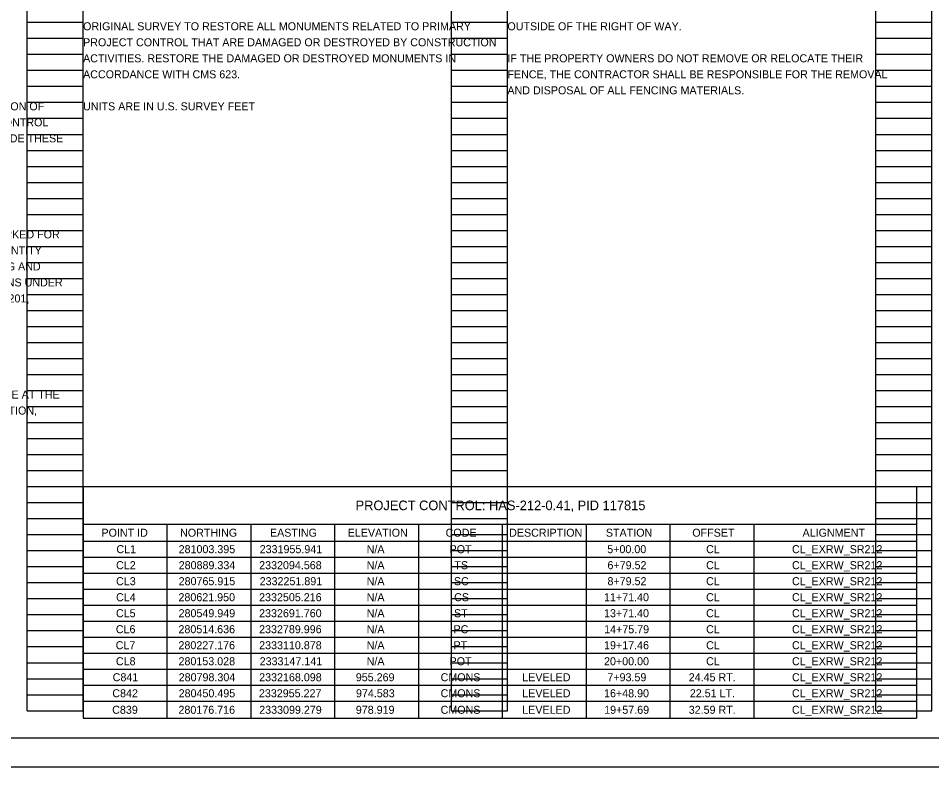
# Model space of a CAD drawing. Extents: x -3.4 to 43.7, y 0 to 26.
# Drawn here: x 8.69 to 24.66, y 0 to 13.09 of the extents above; entities that cross this region are included whole.
import ezdxf

# ---------------------------------------------------------------- set-up
doc = ezdxf.new("R2010")
doc.units = 0
for name, color, linetype in [('SH_Border', 7, 'Continuous'), ('SH_Cut_Line', 7, 'Continuous'), ('SH_Data', 7, 'Continuous'), ('SH_Text', 7, 'Continuous')]:
    doc.layers.add(name, color=color, linetype=linetype)

msp = doc.modelspace()

# ---------------------------------------------------------------- linework, layer by layer
at = {"layer": 'SH_Border'}
msp.add_lwpolyline([(1.5, 21.5), (33.5, 21.5), (33.5, 0.5), (1.5, 0.5)], close=True, dxfattribs=at)
at = {"layer": 'SH_Cut_Line'}
msp.add_lwpolyline([(0, 0), (34, 0), (34, 22), (0, 22)], close=True, dxfattribs=at)
at = {"layer": 'SH_Data'}
for p, q in [((8.84, 0.98), (8.84, 21.14)), ((9.82, 0.98), (9.82, 21.14)), ((16.26, 0.98), (16.26, 21.14)), ((17.24, 0.98), (17.24, 21.14)), ((23.68, 0.98), (23.68, 21.14)), ((24.66, 0.98), (24.66, 21.14)), ((8.84, 13.02), (9.82, 13.02)), ((16.26, 13.02), (17.24, 13.02)), ((23.68, 13.02), (24.66, 13.02)), ((8.84, 12.74), (9.82, 12.74)), ((16.26, 12.74), (17.24, 12.74)), ((23.68, 12.74), (24.66, 12.74)), ((8.84, 12.46), (9.82, 12.46)), ((16.26, 12.46), (17.24, 12.46)), ((23.68, 12.46), (24.66, 12.46)), ((8.84, 12.18), (9.82, 12.18)), ((16.26, 12.18), (17.24, 12.18)), ((23.68, 12.18), (24.66, 12.18)), ((8.84, 11.9), (9.82, 11.9)), ((16.26, 11.9), (17.24, 11.9)), ((23.68, 11.9), (24.66, 11.9)), ((8.84, 11.62), (9.82, 11.62)), ((16.26, 11.62), (17.24, 11.62)), ((23.68, 11.62), (24.66, 11.62)), ((8.84, 11.34), (9.82, 11.34)), ((16.26, 11.34), (17.24, 11.34)), ((23.68, 11.34), (24.66, 11.34)), ((8.84, 11.06), (9.82, 11.06)), ((16.26, 11.06), (17.24, 11.06)), ((23.68, 11.06), (24.66, 11.06)), ((8.84, 10.78), (9.82, 10.78)), ((16.26, 10.78), (17.24, 10.78)), ((23.68, 10.78), (24.66, 10.78)), ((8.84, 10.5), (9.82, 10.5)), ((16.26, 10.5), (17.24, 10.5)), ((23.68, 10.5), (24.66, 10.5)), ((8.84, 10.22), (9.82, 10.22)), ((16.26, 10.22), (17.24, 10.22)), ((23.68, 10.22), (24.66, 10.22)), ((8.84, 9.94), (9.82, 9.94)), ((16.26, 9.94), (17.24, 9.94)), ((23.68, 9.94), (24.66, 9.94)), ((8.84, 9.66), (9.82, 9.66)), ((16.26, 9.66), (17.24, 9.66)), ((23.68, 9.66), (24.66, 9.66)), ((8.84, 9.38), (9.82, 9.38)), ((16.26, 9.38), (17.24, 9.38)), ((23.68, 9.38), (24.66, 9.38)), ((8.84, 9.1), (9.82, 9.1)), ((16.26, 9.1), (17.24, 9.1)), ((23.68, 9.1), (24.66, 9.1)), ((8.84, 8.82), (9.82, 8.82)), ((16.26, 8.82), (17.24, 8.82)), ((23.68, 8.82), (24.66, 8.82)), ((8.84, 8.54), (9.82, 8.54)), ((16.26, 8.54), (17.24, 8.54)), ((23.68, 8.54), (24.66, 8.54)), ((8.84, 8.26), (9.82, 8.26)), ((16.26, 8.26), (17.24, 8.26)), ((23.68, 8.26), (24.66, 8.26)), ((8.84, 7.98), (9.82, 7.98)), ((16.26, 7.98), (17.24, 7.98)), ((23.68, 7.98), (24.66, 7.98)), ((8.84, 7.7), (9.82, 7.7)), ((16.26, 7.7), (17.24, 7.7)), ((23.68, 7.7), (24.66, 7.7)), ((8.84, 7.42), (9.82, 7.42)), ((16.26, 7.42), (17.24, 7.42)), ((23.68, 7.42), (24.66, 7.42)), ((8.84, 7.14), (9.82, 7.14)), ((16.26, 7.14), (17.24, 7.14)), ((23.68, 7.14), (24.66, 7.14)), ((8.84, 6.86), (9.82, 6.86)), ((16.26, 6.86), (17.24, 6.86)), ((23.68, 6.86), (24.66, 6.86)), ((8.84, 6.58), (9.82, 6.58)), ((16.26, 6.58), (17.24, 6.58)), ((23.68, 6.58), (24.66, 6.58)), ((8.84, 6.3), (9.82, 6.3)), ((16.26, 6.3), (17.24, 6.3)), ((23.68, 6.3), (24.66, 6.3)), ((8.84, 6.02), (9.82, 6.02)), ((16.26, 6.02), (17.24, 6.02)), ((23.68, 6.02), (24.66, 6.02)), ((8.84, 5.74), (9.82, 5.74)), ((16.26, 5.74), (17.24, 5.74)), ((23.68, 5.74), (24.66, 5.74)), ((8.84, 5.46), (9.82, 5.46)), ((16.26, 5.46), (17.24, 5.46)), ((23.68, 5.46), (24.66, 5.46)), ((8.84, 5.18), (9.82, 5.18)), ((16.26, 5.18), (17.24, 5.18)), ((23.68, 5.18), (24.66, 5.18)), ((8.84, 4.9), (9.82, 4.9)), ((16.26, 4.9), (17.24, 4.9)), ((23.68, 4.9), (24.66, 4.9)), ((8.84, 4.62), (9.82, 4.62)), ((16.26, 4.62), (17.24, 4.62)), ((23.68, 4.62), (24.66, 4.62)), ((8.84, 4.34), (9.82, 4.34)), ((16.26, 4.34), (17.24, 4.34)), ((23.68, 4.34), (24.66, 4.34)), ((8.84, 4.06), (9.82, 4.06)), ((16.26, 4.06), (17.24, 4.06)), ((23.68, 4.06), (24.66, 4.06)), ((8.84, 3.78), (9.82, 3.78)), ((16.26, 3.78), (17.24, 3.78)), ((23.68, 3.78), (24.66, 3.78)), ((8.84, 3.5), (9.82, 3.5)), ((16.26, 3.5), (17.24, 3.5)), ((23.68, 3.5), (24.66, 3.5)), ((8.84, 3.22), (9.82, 3.22)), ((16.26, 3.22), (17.24, 3.22)), ((23.68, 3.22), (24.66, 3.22)), ((8.84, 2.94), (9.82, 2.94)), ((16.26, 2.94), (17.24, 2.94)), ((23.68, 2.94), (24.66, 2.94)), ((8.84, 2.66), (9.82, 2.66)), ((16.26, 2.66), (17.24, 2.66)), ((23.68, 2.66), (24.66, 2.66)), ((8.84, 2.38), (9.82, 2.38)), ((16.26, 2.38), (17.24, 2.38)), ((23.68, 2.38), (24.66, 2.38)), ((8.84, 2.1), (9.82, 2.1)), ((16.26, 2.1), (17.24, 2.1)), ((23.68, 2.1), (24.66, 2.1)), ((8.84, 1.82), (9.82, 1.82)), ((16.26, 1.82), (17.24, 1.82)), ((23.68, 1.82), (24.66, 1.82)), ((8.84, 1.54), (9.82, 1.54)), ((16.26, 1.54), (17.24, 1.54)), ((23.68, 1.54), (24.66, 1.54)), ((8.84, 1.26), (9.82, 1.26)), ((16.26, 1.26), (17.24, 1.26)), ((23.68, 1.26), (24.66, 1.26)), ((8.84, 0.98), (9.82, 0.98)), ((16.26, 0.98), (17.24, 0.98)), ((23.68, 0.98), (24.66, 0.98))]:
    msp.add_line(p, q, dxfattribs=at)
at = {"layer": 'SH_Text'}
for p, q in [((9.82, 4.9), (24.396, 4.9)), ((9.82, 4.9), (9.82, 0.848)), ((24.396, 4.9), (24.396, 0.848)), ((9.82, 4.241), (24.396, 4.241)), ((11.286, 4.241), (11.286, 0.848)), ((12.752, 4.241), (12.752, 0.848)), ((14.218, 4.241), (14.218, 0.848)), ((15.684, 4.241), (15.684, 0.848)), ((17.149, 4.241), (17.149, 0.848)), ((18.615, 4.241), (18.615, 0.848)), ((20.081, 4.241), (20.081, 0.848)), ((21.547, 4.241), (21.547, 0.848)), ((9.82, 3.945), (24.396, 3.945)), ((9.82, 3.665), (24.396, 3.665)), ((9.82, 3.385), (24.396, 3.385)), ((9.82, 3.105), (24.396, 3.105)), ((9.82, 2.825), (24.396, 2.825)), ((9.82, 2.545), (24.396, 2.545)), ((9.82, 2.265), (24.396, 2.265)), ((9.82, 1.985), (24.396, 1.985)), ((9.82, 1.705), (24.396, 1.705)), ((9.82, 1.425), (24.396, 1.425)), ((9.82, 1.145), (24.396, 1.145)), ((9.82, 0.848), (24.396, 0.848))]:
    msp.add_line(p, q, dxfattribs=at)

# ---------------------------------------------------------------- texts
for s, height, p in [('ORIGINAL SURVEY TO RESTORE ALL MONUMENTS RELATED TO PRIMARY ', 0.14, (9.82, 12.88)), ('OUTSIDE OF THE RIGHT OF WAY.', 0.14, (17.24, 12.88)), ('PROJECT CONTROL THAT ARE DAMAGED OR DESTROYED BY CONSTRUCTION ', 0.14, (9.82, 12.6)), ('ACTIVITIES. RESTORE THE DAMAGED OR DESTROYED MONUMENTS IN ', 0.14, (9.82, 12.32)), ('IF THE PROPERTY OWNERS DO NOT REMOVE OR RELOCATE THEIR ', 0.14, (17.24, 12.32)), ('ACCORDANCE WITH CMS 623.', 0.14, (9.82, 12.04)), ('FENCE, THE CONTRACTOR SHALL BE RESPONSIBLE FOR THE REMOVAL ', 0.14, (17.24, 12.04)), ('AND DISPOSAL OF ALL FENCING MATERIALS.', 0.14, (17.24, 11.76)), ('CONSTRUCTION ONLY. PROVIDE THE INSTALLATION AND OPERATION OF ', 0.14, (2.4, 11.48)), ('UNITS ARE IN U.S. SURVEY FEET', 0.14, (9.82, 11.48)), ('ALL WORK ZONE TRAFFIC CONTROL AND WORK ZONE TRAFFIC CONTROL ', 0.14, (2.4, 11.2)), ('DEVICES REQUIRED BY THESE PLANS WHETHER INSIDE OR OUTSIDE THESE ', 0.14, (2.4, 10.92)), ('ALTHOUGH THERE ARE NO TREES OR STUMPS SPECIFICALLY MARKED FOR ', 0.14, (2.4, 9.24)), ('REMOVAL WITHIN THE LIMITS  OF THE PROJECT, A LUMP SUM QUANTITY ', 0.14, (2.4, 8.96)), ('IS INCLUDED IN THE GENERAL SUMMARY FOR ITEM 201,  CLEARING AND ', 0.14, (2.4, 8.68)), ('GRUBBING. ALL PROVISIONS AS SET FORTH IN THE SPECIFICATIONS UNDER ', 0.14, (2.4, 8.4)), ('THIS ITEM ARE  INCLUDED IN THE LUMP SUM PRICE BID FOR ITEM 201, ', 0.14, (2.4, 8.12)), ('THE FOLLOWING EXISTING PLANS ARE AVAILABLE FOR REFERENCE AT THE ', 0.14, (2.4, 6.44)), ('DISTRICT 11 OFFICE OF THE OHIO DEPARTMENT OF TRANSPORTATION, ', 0.14, (2.4, 6.16)), ('PROJECT CONTROL: HAS-212-0.41, PID 117815', 0.168, (14.585, 4.487)), ('POINT ID', 0.14, (10.141, 4.023)), ('NORTHING', 0.14, (11.516, 4.023)), ('EASTING', 0.14, (13.088, 4.023)), ('ELEVATION', 0.14, (14.447, 4.023)), ('CODE', 0.14, (16.16, 4.023)), ('DESCRIPTION', 0.14, (17.27, 4.023)), ('STATION', 0.14, (18.962, 4.023)), ('OFFSET', 0.14, (20.473, 4.023)), ('ALIGNMENT', 0.14, (22.401, 4.023)), ('CL1', 0.14, (10.403, 3.735)), ('281003.395', 0.14, (11.491, 3.735)), ('2331955.941', 0.14, (12.908, 3.735)), ('N/A', 0.14, (14.779, 3.735)), ('POT', 0.14, (16.229, 3.735)), ('5+00.00', 0.14, (18.986, 3.735)), ('CL', 0.14, (20.715, 3.735)), ('CL_EXRW_SR212', 0.14, (22.216, 3.735)), ('CL2', 0.14, (10.397, 3.455)), ('280889.334', 0.14, (11.492, 3.455)), ('2332094.568', 0.14, (12.899, 3.455)), ('N/A', 0.14, (14.779, 3.455)), ('TS', 0.14, (16.313, 3.455)), ('6+79.52', 0.14, (18.99, 3.455)), ('CL', 0.14, (20.715, 3.455)), ('CL_EXRW_SR212', 0.14, (22.216, 3.455)), ('CL3', 0.14, (10.397, 3.175)), ('280765.915', 0.14, (11.491, 3.175)), ('2332251.891', 0.14, (12.908, 3.175)), ('N/A', 0.14, (14.779, 3.175)), ('SC', 0.14, (16.305, 3.175)), ('8+79.52', 0.14, (18.99, 3.175)), ('CL', 0.14, (20.715, 3.175)), ('CL_EXRW_SR212', 0.14, (22.216, 3.175)), ('CL4', 0.14, (10.397, 2.895)), ('280621.950', 0.14, (11.488, 2.895)), ('2332505.216', 0.14, (12.898, 2.895)), ('N/A', 0.14, (14.779, 2.895)), ('CS', 0.14, (16.309, 2.895)), ('11+71.40', 0.14, (18.93, 2.895)), ('CL', 0.14, (20.715, 2.895)), ('CL_EXRW_SR212', 0.14, (22.216, 2.895)), ('CL5', 0.14, (10.395, 2.615)), ('280549.949', 0.14, (11.49, 2.615)), ('2332691.760', 0.14, (12.898, 2.615)), ('N/A', 0.14, (14.779, 2.615)), ('ST', 0.14, (16.306, 2.615)), ('13+71.40', 0.14, (18.93, 2.615)), ('CL', 0.14, (20.715, 2.615)), ('CL_EXRW_SR212', 0.14, (22.216, 2.615)), ('CL6', 0.14, (10.393, 2.335)), ('280514.636', 0.14, (11.488, 2.335)), ('2332789.996', 0.14, (12.898, 2.335)), ('N/A', 0.14, (14.779, 2.335)), ('PC', 0.14, (16.298, 2.335)), ('14+75.79', 0.14, (18.932, 2.335)), ('CL', 0.14, (20.715, 2.335)), ('CL_EXRW_SR212', 0.14, (22.216, 2.335)), ('CL7', 0.14, (10.39, 2.055)), ('280227.176', 0.14, (11.488, 2.055)), ('2333110.878', 0.14, (12.899, 2.055)), ('N/A', 0.14, (14.779, 2.055)), ('PT', 0.14, (16.298, 2.055)), ('19+17.46', 0.14, (18.93, 2.055)), ('CL', 0.14, (20.715, 2.055)), ('CL_EXRW_SR212', 0.14, (22.216, 2.055)), ('N/A', 0.14, (14.779, 1.775)), ('CL8', 0.14, (10.394, 1.775)), ('280153.028', 0.14, (11.489, 1.775)), ('2333147.141', 0.14, (12.908, 1.775)), ('POT', 0.14, (16.229, 1.775)), ('20+00.00', 0.14, (18.93, 1.775)), ('CL', 0.14, (20.715, 1.775)), ('CL_EXRW_SR212', 0.14, (22.216, 1.775)), ('C841', 0.14, (10.338, 1.495)), ('280798.304', 0.14, (11.492, 1.495)), ('2332168.098', 0.14, (12.899, 1.495)), ('955.269', 0.14, (14.589, 1.495)), ('CMONS', 0.14, (16.072, 1.495)), ('LEVELED', 0.14, (17.5, 1.495)), ('7+93.59', 0.14, (18.988, 1.495)), ('24.45 RT.', 0.14, (20.411, 1.495)), ('CL_EXRW_SR212', 0.14, (22.216, 1.495)), ('C842', 0.14, (10.331, 1.215)), ('280450.495', 0.14, (11.491, 1.215)), ('2332955.227', 0.14, (12.895, 1.215)), ('974.583', 0.14, (14.592, 1.215)), ('CMONS', 0.14, (16.072, 1.215)), ('LEVELED', 0.14, (17.5, 1.215)), ('16+48.90', 0.14, (18.93, 1.215)), ('22.51 LT.', 0.14, (20.43, 1.215)), ('CL_EXRW_SR212', 0.14, (22.216, 1.215)), ('C839', 0.14, (10.329, 0.926)), ('280176.716', 0.14, (11.488, 0.926)), ('2333099.279', 0.14, (12.9, 0.926)), ('978.919', 0.14, (14.589, 0.926)), ('CMONS', 0.14, (16.072, 0.926)), ('LEVELED', 0.14, (17.5, 0.926)), ('19+57.69', 0.14, (18.932, 0.926)), ('32.59 RT.', 0.14, (20.411, 0.926)), ('CL_EXRW_SR212', 0.14, (22.216, 0.926))]:
    msp.add_text(s, height=height, dxfattribs=at).set_placement(p)

doc.saveas('drawing.dxf')
